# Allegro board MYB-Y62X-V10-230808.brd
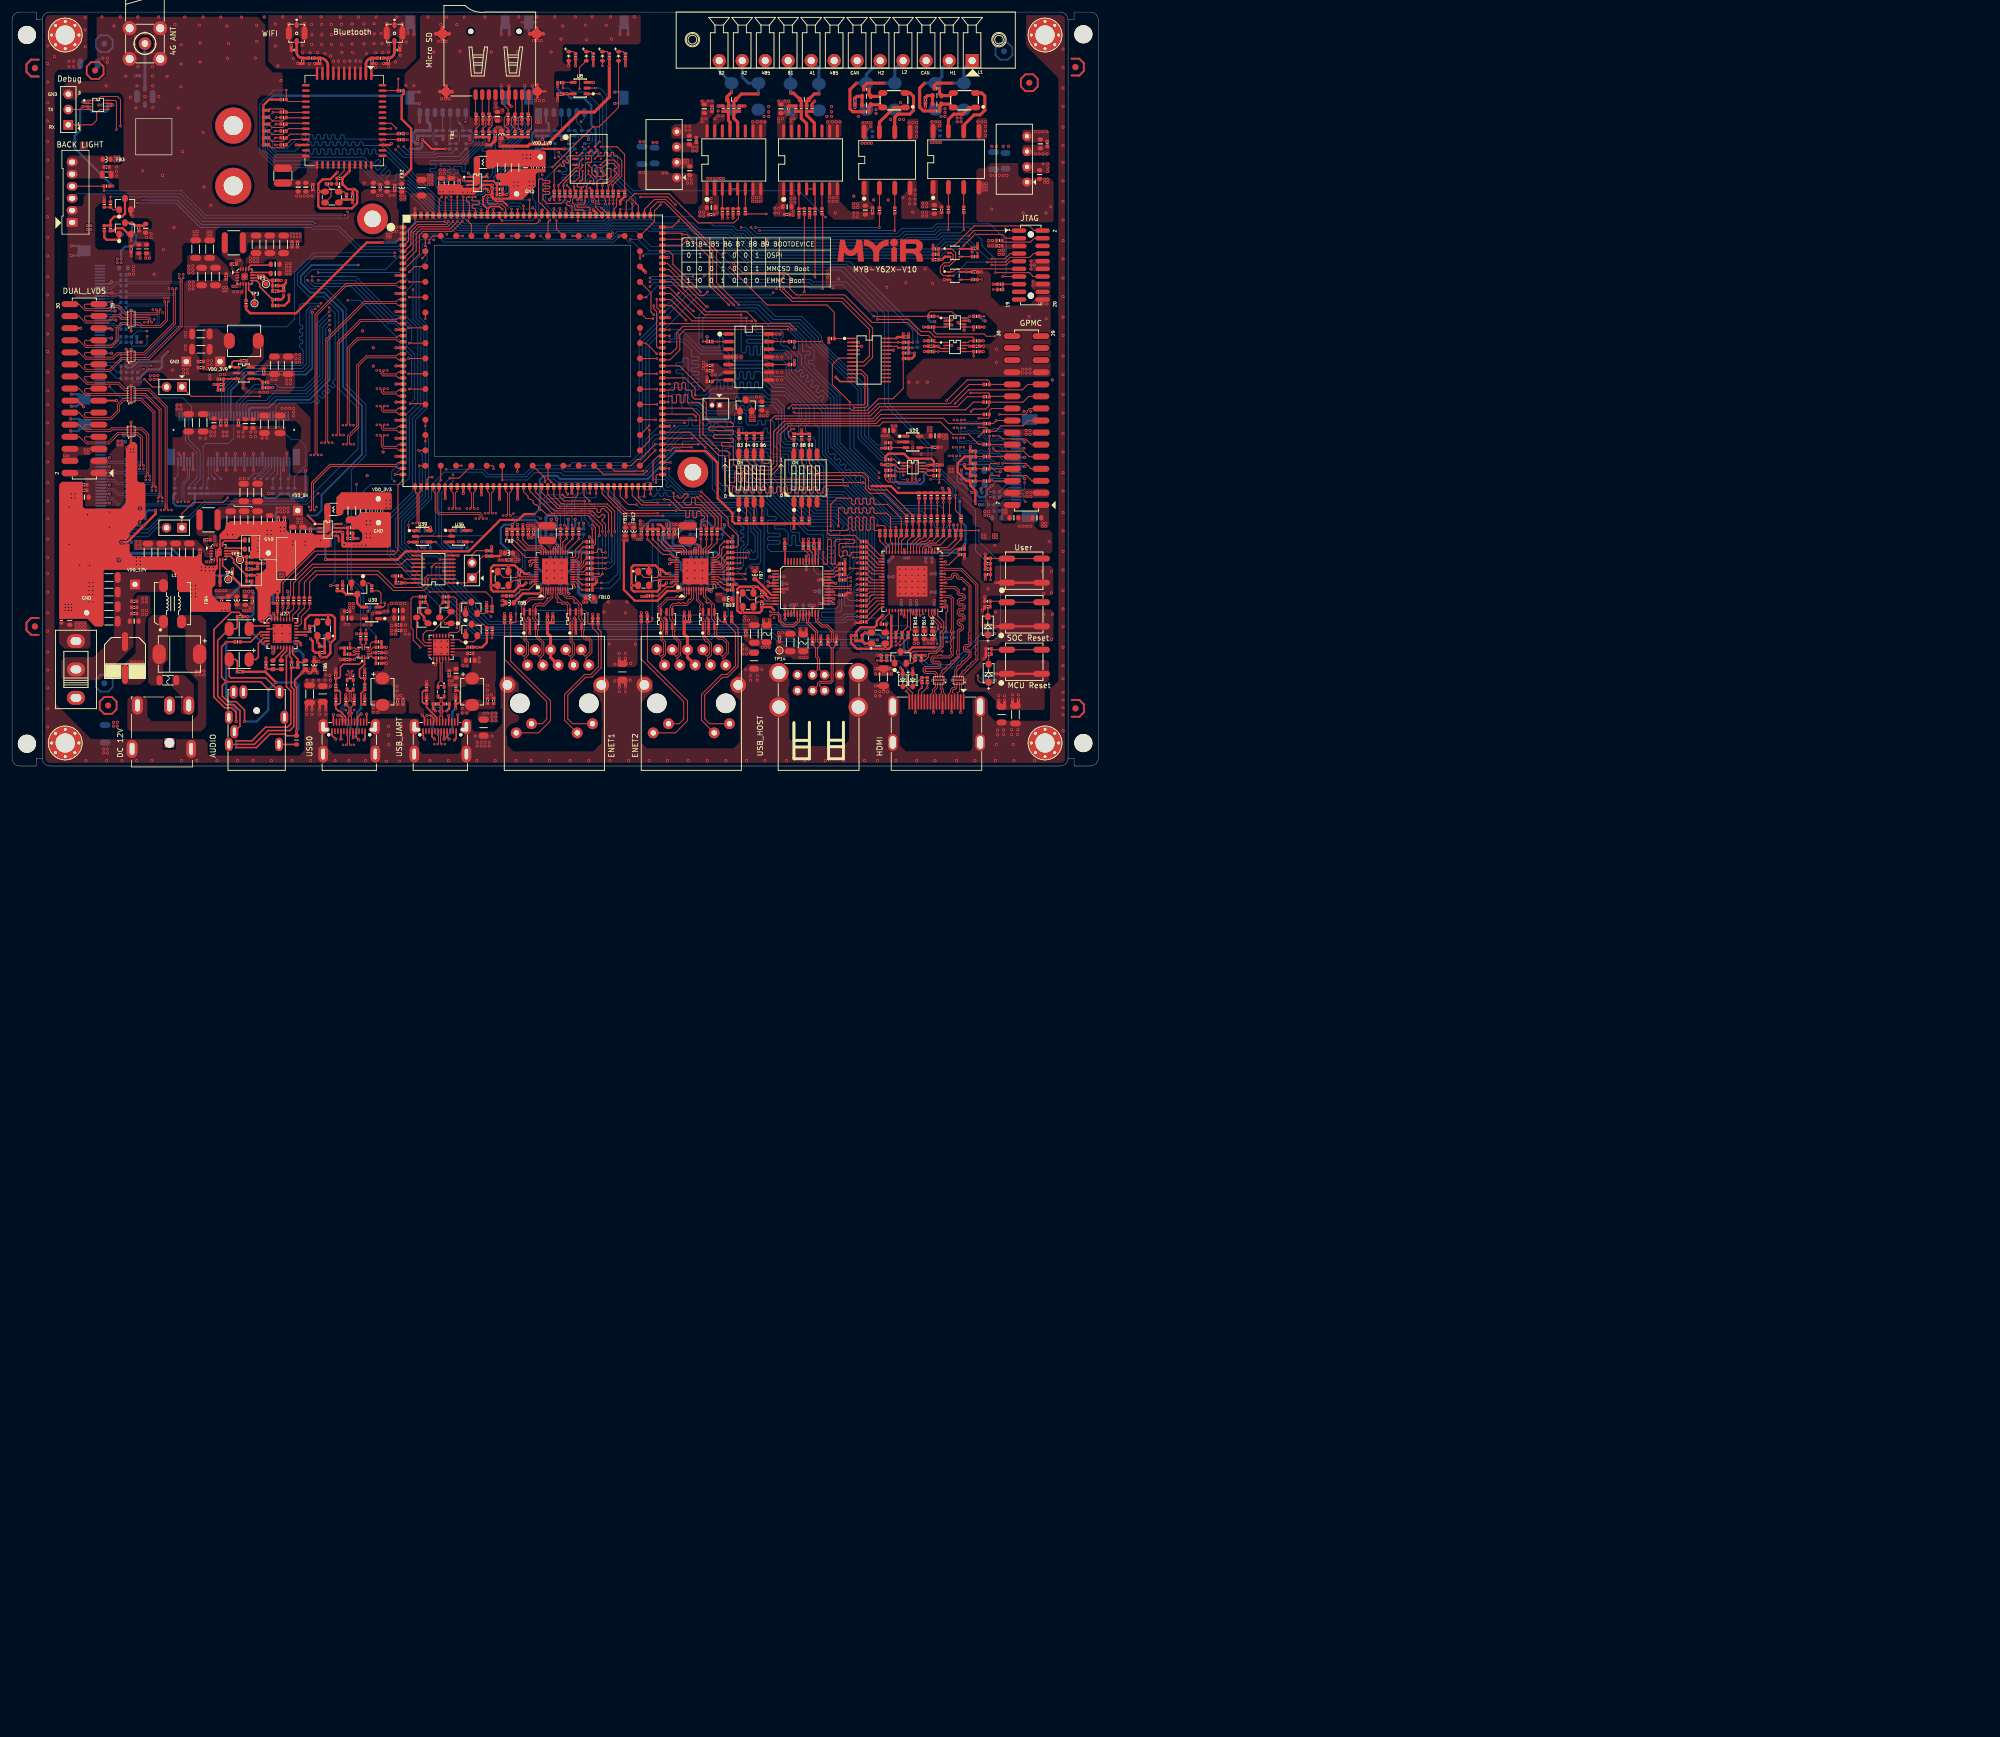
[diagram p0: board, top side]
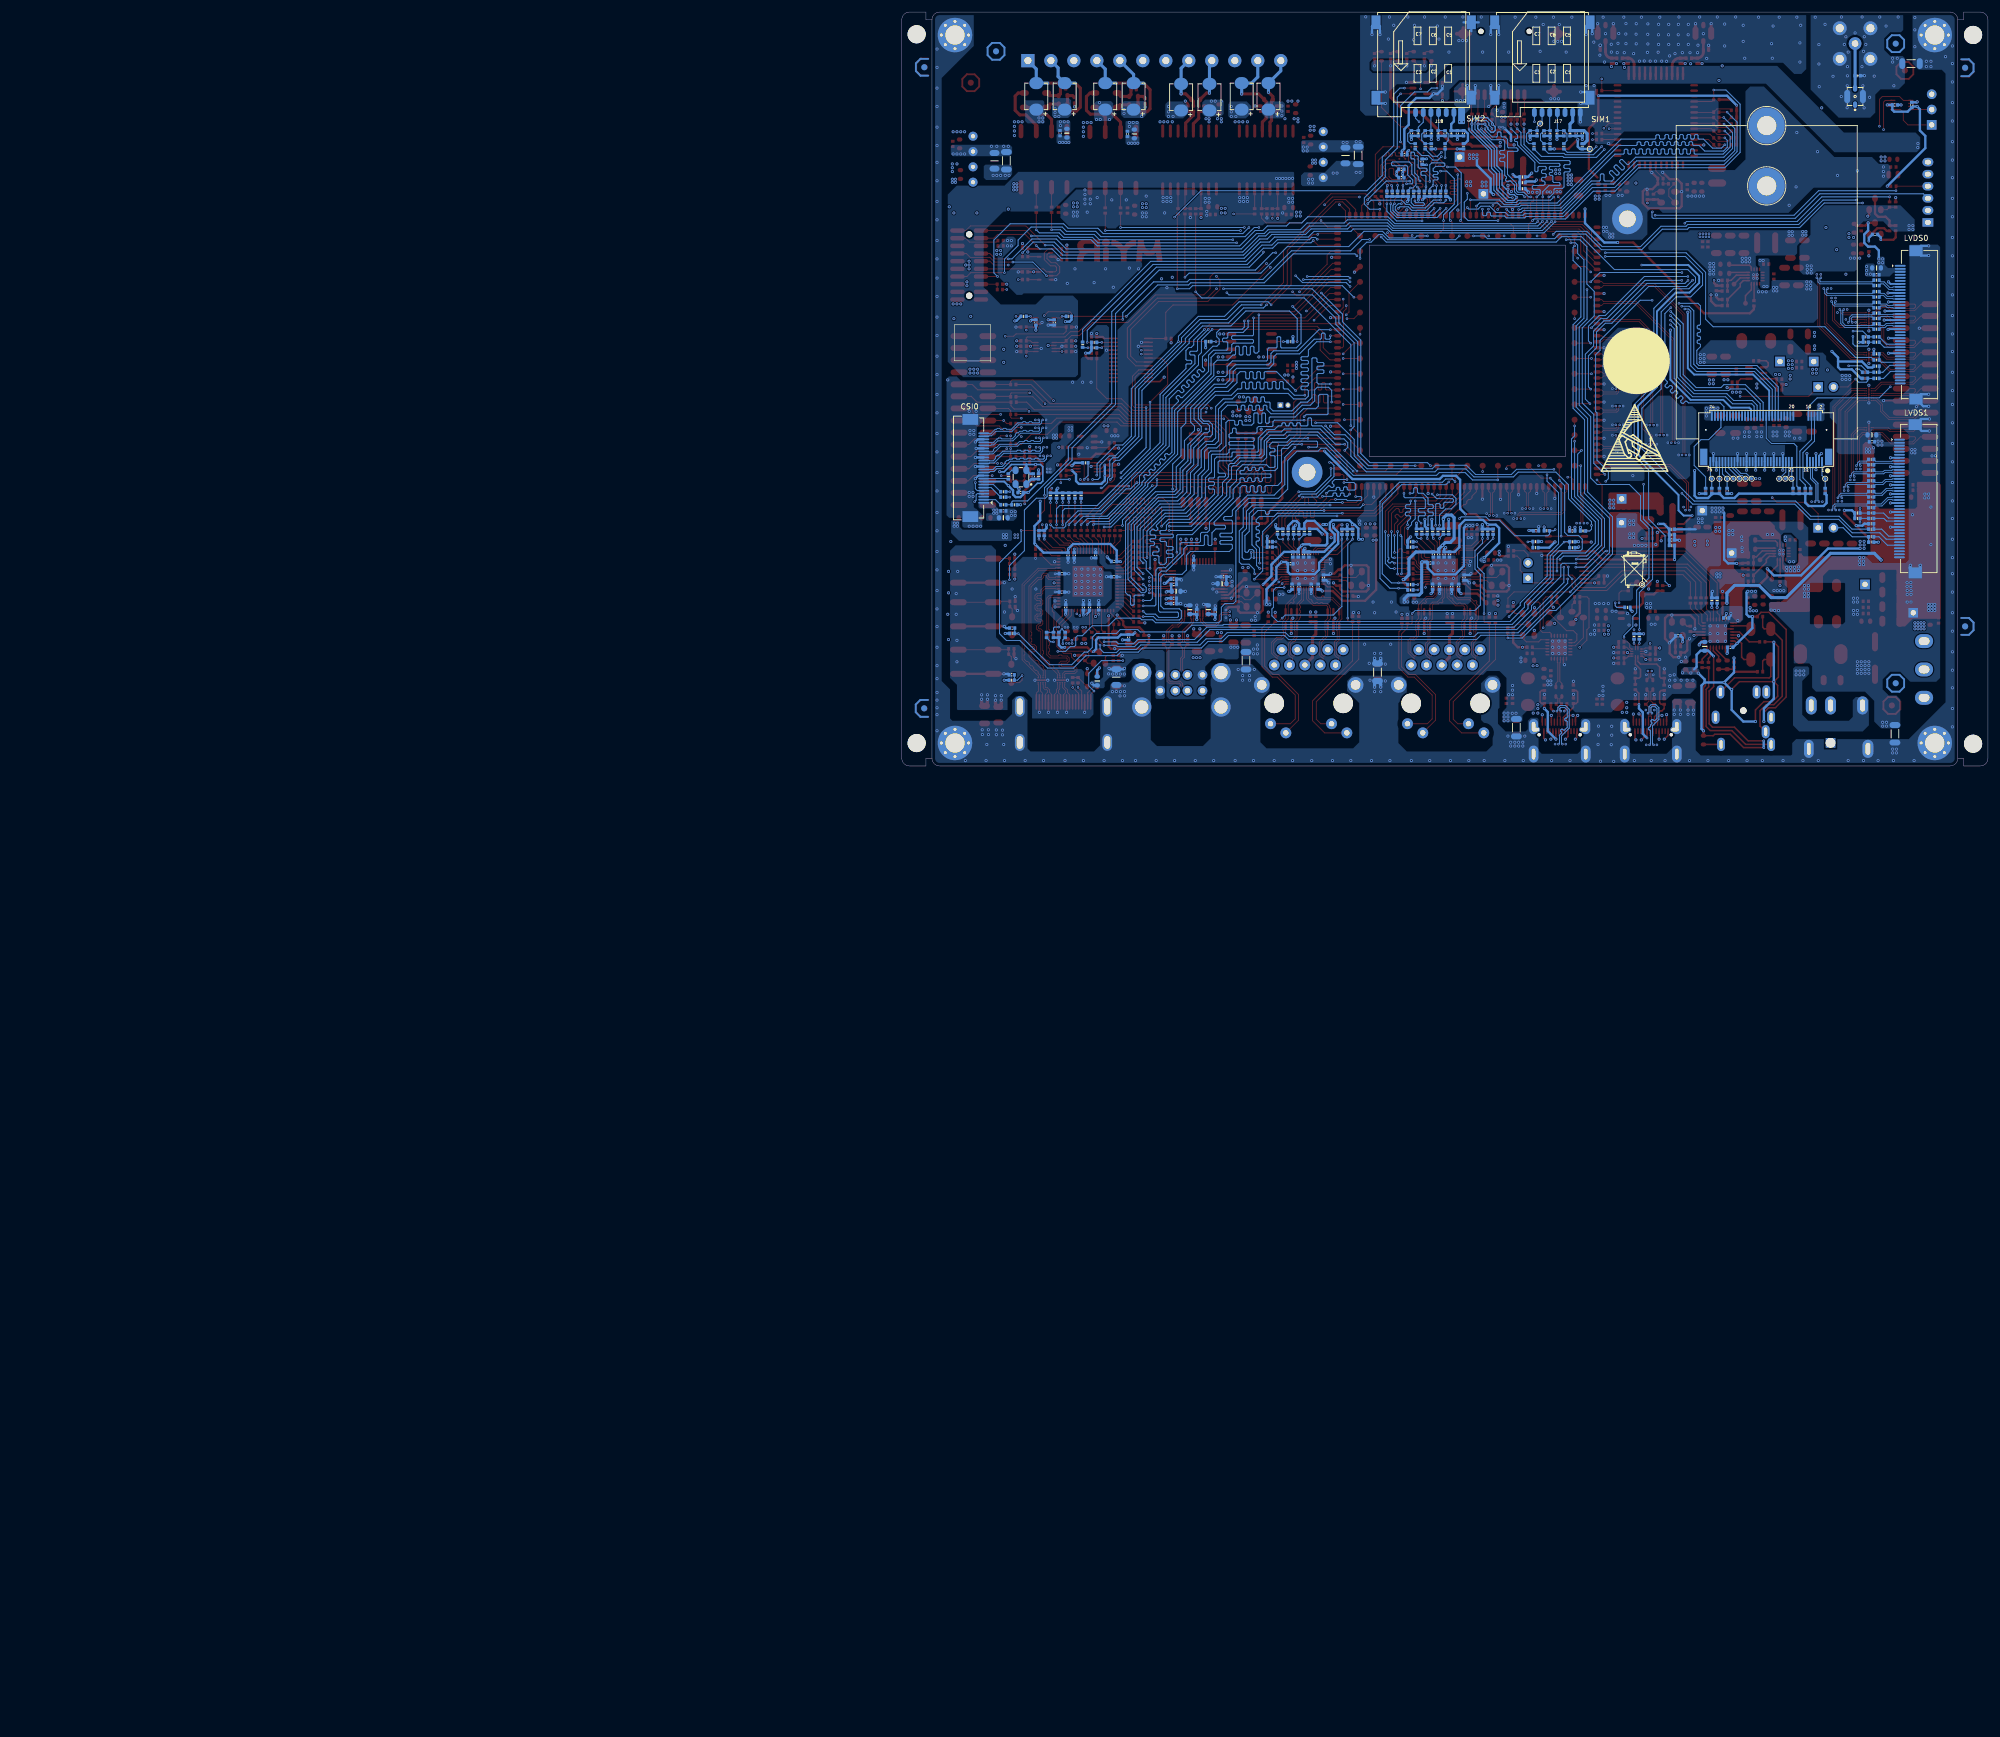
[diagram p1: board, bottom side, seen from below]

Outline 180 x 125 mm; copper layers: TOP, GND02, ART03, POW04, GND05, BOTTOM. Coordinates in mm from the lower left corner of the outline.
Outline path: 5,123.73 4,123.73 4,125 1.27,125 arc(0.37,124.63) 0,123.73 0,1.27 arc(0.37,0.37) 1.27,0 4,0 4,1.27 5,1.27 ; 5,123.73 arc(5.37,124.63) 6.27,125 173.73,125 arc(174.63,124.63) 175,123.73 ; 5,123.73 5,1.27 ; 5,1.27 arc(5.37,0.37) 6.27,0 173.73,0 arc(174.63,0.37) 175,1.27 ; 175,123.73 175,1.27 ; 175,123.73 176,123.73 176,125 178.73,125 arc(179.63,124.63) 180,123.73 180,1.27 arc(179.63,0.37) 178.73,0 176,0 176,1.27 175,1.27 ; 70.02,86.36 70.02,51.31 102.54,51.31 102.54,86.36 70.02,86.36

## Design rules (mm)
net group AUD_MCASP0_ACLKX: nets AUD_MCASP0_ACLKX I2S_SCLK
net group AUD_MCASP0_AFSX: nets AUD_MCASP0_AFSX I2S_LRCLK
net group AUD_MIC: nets AUD_MIC MIC_BIAS
net group AUDIO_MCLK: nets AUDIO_MCLK N20656670
net group CAM_P1_MCLK: nets CAM_P1_MCLK N20386876
net group CAM_RST: nets CAM_RST N20386882
net group CANH1: nets CANH1 N22767928
net group CANH2: nets CANH2 N22768270
net group CANL1: nets CANL1 N22767957
net group CSI_PWDN: nets CSI_PWDN N20386885
net group DEBUG_USB: nets DEBUG_USB_DM DEBUG_USB_DP
net group DIFFPAIR0: nets N22324946 N22324958
net group DPETH1_MD1_: nets ETH1_MD1_N ETH1_MD1_P
net group DPETH1_MD2_: nets ETH1_MD2_N ETH1_MD2_P
net group DPETH1_MD3_: nets ETH1_MD3_N ETH1_MD3_P
net group DPETH1_MD4_: nets ETH1_MD4_N ETH1_MD4_P
net group DPETH2_MD1_: nets ETH2_MD1_N ETH2_MD1_P
net group DPETH2_MD2_: nets ETH2_MD2_N ETH2_MD2_P
net group DPETH2_MD3_: nets ETH2_MD3_N ETH2_MD3_P
net group DPETH2_MD4_: nets ETH2_MD4_N ETH2_MD4_P
net group DPLVDS0_CLK: nets LVDS0_CLKN LVDS0_CLKP
net group DPLVDS0_D0: nets LVDS0_D0N LVDS0_D0P
net group DPLVDS0_D1: nets LVDS0_D1N LVDS0_D1P
net group DPLVDS0_D2: nets LVDS0_D2N LVDS0_D2P
net group DPLVDS0_D3: nets LVDS0_D3N LVDS0_D3P
net group DPLVDS1_CLK: nets LVDS1_CLKN LVDS1_CLKP
net group DPLVDS1_D0: nets LVDS1_D0N LVDS1_D0P
net group DPLVDS1_D1: nets LVDS1_D1N LVDS1_D1P
net group DPLVDS1_D2: nets LVDS1_D2N LVDS1_D2P
net group DPLVDS1_D3: nets LVDS1_D3N LVDS1_D3P
net group HDMI_CONN_CLK: nets HDMI_CONN_CLKN HDMI_CONN_CLKP
net group HDMI_CONN_TX0: nets HDMI_CONN_TX0N HDMI_CONN_TX0P
net group HDMI_CONN_TX1: nets HDMI_CONN_TX1N HDMI_CONN_TX1P
net group HDMI_CONN_TX2: nets HDMI_CONN_TX2N HDMI_CONN_TX2P
net group HDMI_I2C_SCL: nets HDMI_I2C_SCL N22724271
net group HDMI_I2C_SDA: nets HDMI_I2C_SDA N22724282
net group HDMI_MCASP0_ACLKX: nets HDMI_MCASP0_ACLKX N22857632
net group HDMI_MCASP0_AFSX: nets HDMI_MCASP0_AFSX N22857662
net group HDMI_MCASP0_AXR: nets HDMI_MCASP0_AXR N22710530
net group HDMI_MCLK: nets HDMI_MCLK MCLK_12M
net group I2S_DIN: nets AUD_MCASP0_AXR0 I2S_DIN
net group I2S_DOUT: nets AUD_MCASP0_AXR1 I2S_DOUT
net group JTAG_CTI_RTCK: nets JTAG_CTI_RTCK N22483568
net group JTAG_CTI_TCK: nets JTAG_CTI_TCK N22483498
net group JTAG_EMU_RSTN: nets JTAG_EMU_RSTN JTAG_EMU_RSTN_R
net group LCD_TP_INTN: nets LCD_TP_INTN LCD_TP_INTN_R
net group LCD_TP_RESET: nets LCD_TP_RESET LCD_TP_RESET_R
net group LVDS0_TP_PEN: nets LVDS0_TP_PEN N22348696
net group LVDS1_TP_PEN: nets LVDS1_TP_PEN N22355619
net group N22683837: nets N22683837 N22683839
net group N22683997: nets N22683997 N22684003
net group OSPI_INTN: nets OSPI_INTN SOC_OSPI0_ECC_FAIL
net group SOC-USB0: nets SOC_USB0_DM SOC_USB0_DP
net group SOC-USB1: nets SOC_USB1_DM SOC_USB1_DP
net group SOC_GPMC0_WAIT1: nets N21683802 SOC_GPMC0_WAIT1
net group SOC_GPMC0_WPN: nets N21683857 SOC_GPMC0_WPN
net group SOC_JTAG_TCK: nets N22483474 SOC_JTAG_TCK
net group SOC_MCU_MCAN0_RX: nets N22767970 SOC_MCU_MCAN0_RX
net group SOC_MCU_MCAN0_TX: nets N22767924 SOC_MCU_MCAN0_TX
net group SOC_MCU_SPI0_D0: nets N20386918 SOC_MCU_SPI0_D0
net group SOC_OSPI0_DQS: nets SOC_OSPI0_DQS SOC_OSPI0_LBCLK
net group SOC_SPI0_CS0: nets N22355541 SOC_SPI0_CS0
net group SOC_SPI0_CS1: nets N22348627 SOC_SPI0_CS1
net group SOC_SPI0_D0: nets N22348634 SOC_SPI0_D0
net group SOC_SPI0_D1: nets N22355547 SOC_SPI0_D1
net group SOC_UART0_TXD: nets N22941387 SOC_UART0_TXD
net group SOC_UART1_DTRN: nets N22768266 SOC_UART1_DTRN
net group SOC_UART1_RIN: nets N22768318 SOC_UART1_RIN
net group SOC_UART1_RXD: nets N22683943 SOC_UART1_RXD
net group SOC_UART1_TXD: nets N22683961 SOC_UART1_TXD
net group SOC_UART4_RXD: nets N21684314 SOC_UART4_RXD
net group SOC_UART4_TXD: nets N21684387 SOC_UART4_TXD
net group SOC_USB0_DRVVBUS: nets N22325338 SOC_USB0_DRVVBUS
net group SOC_USB1_DRVVBUS: nets N21683929 SOC_USB1_DRVVBUS
net group USB0CC1: nets N22325125 USB0CC1
net group USB0CC2: nets N22325136 USB0CC2
net group USB-5G: nets USB_5G_DM USB_5G_DP
net group USB-UART: nets USB_UART_DM USB_UART_DP
net group USB_HUB_RST: nets N21477956 USB_HUB_RST
net group USBA0: nets USBA0_DM USBA0_DP
net group USBA1: nets USBA1_DM USBA1_DP
net group VDD_USIM1: nets N21544762 VDD_USIM1
net group VDD_USIM2: nets N24926165 VDD_USIM2
net group 50 OHM: nets N25388780
net group AUDIO_GND: nets HP_VGND
net group AUDIO_I2C_SCL: nets AUDIO_I2C_SCL I2C_SCL_CSI LCD_I2C_SCL N22863110 SOC_UART1_DCDN
net group CANL2: nets CANL2 N22768305 N22768352
net group HDMI_TX: nets HDMI_CLK+ HDMI_CLK- HDMI_TX0+ HDMI_TX0- HDMI_TX1+ HDMI_TX1- HDMI_TX2+ HDMI_TX2-
net group I2C_SDA_CSI: nets AUDIO_I2C_SDA I2C_SDA_CSI LCD_I2C_SDA SOC_UART1_DSRN
net group ISO_485: nets N21683845 N21683901 N21714485 N21714524 RS485_A1 RS485_A2 RS485_B1 RS485_B2
net group LCD_B3: nets LCD_B3
net group LCD_B4: nets LCD_B4
net group LCD_B5: nets LCD_B5
net group LCD_B6: nets LCD_B6
net group LCD_B7: nets LCD_B7
net group LCD_G1: nets LCD_G1
net group LCD_G2: nets LCD_G2
net group LCD_G4: nets LCD_G4
net group LCD_G5: nets LCD_G5
net group LCD_G6: nets LCD_G6
net group LCD_G7: nets LCD_G7
net group LCD_R0: nets LCD_R0
net group LCD_R1: nets LCD_R1
net group LCD_R2: nets LCD_R2
net group LCD_R3: nets LCD_R3
net group LCD_R4: nets LCD_R4
net group LVDS0_I2C_SCL: nets LVDS0_I2C_SCL N22597309 SOC_I2C1_SCL SOC_I2C1_SCL_R
net group LVDS0_I2C_SDA: nets LVDS0_I2C_SDA SOC_I2C1_SDA SOC_I2C1_SDA_R
net group LVDS1_I2C_SCL: nets LVDS1_I2C_SCL N22863348 RTC_I2C_SCL USB_I2C_SCL
net group LVDS1_I2C_SDA: nets LVDS1_I2C_SDA RTC_I2C_SDA SOC_UART0_RTSN USB_I2C_SDA
net group N20390757: nets N20390701
net group PWR: nets DEBUG_USB_CC1 DEBUG_USB_CC2 DVDD_RGMII1 DVDD_RGMII2 VDD_MMC1_SD VDD_USB_PLL VDDA_PHY1_3V3
net group RST: nets BT_RST ETH1_RST ETH2_RST
net group RST/CLK: nets MODULE_RESET_N OSPI_RSTN SOC_EXT_REFCLK1 SOC_MCU_RESETZ SOC_MCU_SPI0_CLK SOC_SPI0_CLK

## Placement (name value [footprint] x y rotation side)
C1  100nF/4/50V  [C0402]  20.24 27.3 0 top
C2  100nF/4/50V  [C0402]  20.24 25.27 0 top
C3  1uF/6/25V  [C0603]  20.24 24 0 top
C4  100nF/4/50V  [C0402]  20.24 26.29 0 top
C5  22uF/12/25V  [C1206]  16.05 24 180 top
C6  100uF/6x7/25V  [CE6X6]  18.72 17.91 180 top
C7  1nF/12/2kV  [C1206]  15.41 5.33 90 bottom
C8  1nF/12/2kV  [C1206]  12.75 116.46 0 bottom
C9  1uF/6/25V  [C0603]  43.61 83.19 0 top
C10  22uF/12/25V  [C1206]  31.42 81.15 270 top
C11  100nF/4/50V  [C0402]  36.75 83.21 0 top
C12  22uF/12/25V  [C1206]  33.7 81.15 270 top
C13  100nF/4/50V  [C0402]  35.48 81.15 270 top
C14  10nF/4/50V  [C0402]  47.29 86.49 270 top
C15  47uF/12/10V  [C1206]  40.43 86.49 270 top
C16  47uF/12/10V  [C1206]  42.72 86.49 270 top
C17  47uF/12/10V  [C1206]  45 86.49 270 top
C18  100nF/4/50V  [C0402]  46.4 86.49 270 top
C19  2.2nF/4/50V  [C0402]  43.61 78.74 180 top
C20  1uF/6/25V  [C0603]  43.61 81.66 0 top
C21  1uF/6/25V  [C0603]  39.29 37.47 0 top
C22  22uF/12/25V  [C1206]  27.1 35.43 270 top
C23  22uF/12/25V  [C1206]  29.38 35.43 270 top
C24  100nF/4/50V  [C0402]  31.16 35.43 270 top
C25  100nF/4/50V  [C0402]  32.38 37.49 0 top
C26  10nF/4/50V  [C0402]  44.12 40.77 270 top
C27  47uF/12/10V  [C1206]  36.24 40.77 270 top
C28  47uF/12/10V  [C1206]  38.45 40.79 270 top
C29  47uF/12/10V  [C1206]  40.69 40.77 270 top
C30  100nF/4/50V  [C0402]  45.13 40.77 270 top
C31  2.2nF/4/50V  [C0402]  39.29 32.64 180 top
C32  1uF/6/25V  [C0603]  39.29 35.94 0 top
C33  22uF/8/10V  [C0805]  48.18 38.86 270 top
C34  22uF/8/10V  [C0805]  46.53 38.86 270 top
C35  100nF/4/50V  [C0402]  49.45 38.86 270 top
C36  1nF/4/50V  [C0402]  80.82 94.74 180 top
C37  1nF/4/50V  [C0402]  56.05 37.72 180 top
C38  10nF/4/50V  [C0402]  59.48 42.29 270 top
C39  47uF/12/10V  [C1206]  56.31 42.29 270 top
C40  22uF/8/10V  [C0805]  58.21 42.29 270 top
C41  100nF/4/50V  [C0402]  61.26 42.29 270 top
C42  100nF/4/50V  [C0402]  60.37 42.29 270 top
C43  22uF/8/10V  [C0805]  72.82 96.67 270 top
C44  100nF/4/50V  [C0402]  74.09 96.67 270 top
C45  100nF/4/50V  [C0402]  87.12 99.19 270 top
C46  10uF/4/6.3V  [C0402]  86.23 99.19 270 top
C47  22uF/6/6.3V  [C0603]  85.09 99.19 270 top
C54  100nF/4/50V  [C0402]  80.06 104.73 270 top
C55  2.2uF/6/16V  [C0603]  80.44 107.7 270 top
C56  100nF/4/50V  [C0402]  97.2 97.54 0 bottom
C57  100nF/4/50V  [C0402]  90.85 111.38 180 top
C58  100nF/4/50V  [C0402]  96.69 101.35 180 bottom
C59  4.7uF/4/6.3V  [C0402]  93.77 100.2 90 bottom
C60  100nF/4/50V  [C0402]  97.2 98.93 0 bottom
C61  100nF/4/50V  [C0402]  63.42 95.84 270 top
C62  10uF/6/16V  [C0603]  62.15 95.97 270 top
C65  100nF/4/50V  [C0402]  163.62 86.23 180 top
C70  100nF/4/50V  [C0402]  159.56 85.85 0 top
C71  100nF/4/50V  [C0402]  159.56 81.92 0 top
C72  10pF/4/50V  [C0402]  153.08 83.95 0 top
C73  10uF/6/16V  [C0603]  18.46 82.58 0 bottom
C74  10uF/6/16V  [C0603]  19.22 54.89 0 bottom
C75  100nF/4/50V  [C0402]  18.46 81.43 0 bottom
C76  100nF/4/50V  [C0402]  19.22 53.75 0 bottom
C77  100nF/4/50V  [C0402]  19.73 85.72 270 top
C78  100nF/4/50V  [C0402]  18.72 88.14 180 bottom
C79  10uF/6/16V  [C0603]  22.14 89.15 270 top
C80  100nF/4/50V  [C0402]  21 89.15 270 top
C81  10uF/8/25V  [C0805]  15.67 98.04 0 top
C82  100nF/4/50V  [C0402]  15.67 99.31 0 top
C83  100nF/4/50V  [C0402]  163.18 42.29 180 bottom
C84  10uF/6/16V  [C0603]  163.18 41.15 180 bottom
C85  100nF/4/50V  [C0402]  160.32 45.34 180 bottom
C86  100nF/4/50V  [C0402]  158.22 48.01 90 bottom
C87  100nF/4/50V  [C0402]  152.32 69.6 180 top
C88  100nF/4/50V  [C0402]  159.81 69.6 0 top
C89  10uF/6/16V  [C0603]  145.33 55.63 180 top
C90  10uF/6/16V  [C0603]  147.62 14.1 270 bottom
C91  10uF/6/16V  [C0603]  169.85 41.15 180 top
C92  10uF/6/16V  [C0603]  166.04 41.15 0 top
C93  100nF/4/50V  [C0402]  78.79 10.79 90 top
C94  10pF/4/50V  [C0402]  79.8 10.79 90 top
C95  100nF/4/50V  [C0402]  75.93 18.67 0 top
C96  1uF/6/25V  [C0603]  73.58 15.37 270 top
C97  10uF/6/16V  [C0603]  75.93 17.53 0 top
C98  100nF/4/50V  [C0402]  72.44 15.37 270 top
C99  DNP/C1206  [C1206]  78.15 6.35 270 bottom
C100  10uF/6/16V  [C0603]  152.84 92.29 270 top
C101  100nF/4/50V  [C0402]  154.03 92.22 270 top
C102  100nF/4/50V  [C0402]  153.78 104.92 270 bottom
C103  10uF/6/16V  [C0603]  152.63 104.92 270 bottom
C104  47nF/4/50V  [C0402]  151.36 110.38 270 top
C105  10uF/6/16V  [C0603]  170.29 98.06 270 top
C106  10uF/6/16V  [C0603]  170.41 103.14 270 top
C107  DNP/C1206  [C1206]  162.67 100.35 90 bottom
C108  10uF/6/16V  [C0603]  141.41 92.16 270 top
C109  100nF/4/50V  [C0402]  142.6 92.09 270 top
C110  100nF/4/50V  [C0402]  142.6 104.79 270 bottom
C111  10uF/6/16V  [C0603]  141.46 104.79 270 bottom
C112  47nF/4/50V  [C0402]  139.68 110.26 270 top
C113  10uF/6/16V  [C0603]  112.31 98.68 270 top
C114  10uF/6/16V  [C0603]  112.25 103.78 270 top
C115  10uF/6/16V  [C0603]  128.44 92.71 0 top
C116  100nF/4/50V  [C0402]  128.44 91.44 0 top
C117  100nF/4/50V  [C0402]  128.7 108.97 90 top
C118  10uF/6/16V  [C0603]  127.43 108.97 90 top
C119  DNP/C1206  [C1206]  104.37 101.24 90 bottom
C121  10uF/6/16V  [C0603]  115.87 92.58 0 top
C122  100nF/4/50V  [C0402]  115.87 91.44 0 top
C123  100nF/4/50V  [C0402]  116 108.97 90 top
C124  10uF/6/16V  [C0603]  114.73 108.97 90 top
C125  100nF/4/50V  [C0402]  51.35 21.59 0 bottom
C126  100nF/4/50V  [C0402]  51.35 18.8 180 top
C127  100nF/4/50V  [C0402]  46.33 16.74 90 top
C128  1nF/4/50V  [C0402]  37.77 24.77 0 top
C129  1nF/4/50V  [C0402]  37.77 15.62 0 top
C130  1uF/6/25V  [C0603]  48.64 16.74 270 top
C131  100nF/4/50V  [C0402]  42.72 19.68 180 bottom
C132  DNP  [C0603]  46.94 19.84 270 bottom
C133  1uF/6/25V  [C0603]  35.86 27.43 270 top
C134  100nF/4/50V  [C0402]  34.72 27.43 270 top
C135  1uF/6/25V  [C0603]  38.65 27.43 90 top
C136  100nF/4/50V  [C0402]  39.8 27.43 90 top
C137  100nF/4/50V  [C0402]  43.99 27.43 90 top
C138  100nF/4/50V  [C0402]  132.89 36.45 90 top
C139  10uF/6/16V  [C0603]  129.21 25.91 90 bottom
C140  1uF/6/25V  [C0603]  132.25 25.91 90 bottom
C141  100nF/4/50V  [C0402]  131.62 33.66 270 bottom
C142  100nF/4/50V  [C0402]  134.92 30.99 180 bottom
C143  100nF/4/50V  [C0402]  131.11 25.53 90 bottom
C144  100nF/4/50V  [C0402]  128.06 25.53 90 bottom
C145  100nF/4/50V  [C0402]  134.92 27.81 180 bottom
C146  22pF/4/50V  [C0402]  124.25 26.8 270 top
C147  22pF/4/50V  [C0402]  124.25 28.57 90 top
C148  10uF/6/16V  [C0603]  126.92 30.23 0 bottom
C149  1uF/6/25V  [C0603]  134.54 28.96 180 bottom
C150  100nF/4/50V  [C0402]  134.92 30.1 180 bottom
C151  100nF/4/50V  [C0402]  134.92 26.92 180 bottom
C152  100nF/4/50V  [C0402]  126.67 31.37 0 bottom
C153  100nF/4/50V  [C0402]  55.55 17.65 180 top
C154  100nF/4/50V  [C0402]  60.75 18.8 0 top
C155  100nF/4/50V  [C0402]  63.9 10.67 90 top
C156  10pF/4/50V  [C0402]  64.79 10.67 90 top
C157  10uF/6/16V  [C0603]  55.55 24.51 180 top
C158  1nF/4/50V  [C0402]  53.64 14.99 90 top
C159  100nF/4/50V  [C0402]  55.55 25.65 180 top
C160  1nF/4/50V  [C0402]  58.44 14.99 90 top
C161  4.7uF/6/16V  [C0603]  64.05 25.78 0 top
C162  100nF/4/50V  [C0402]  64.05 22.48 0 top
C163  100nF/4/50V  [C0402]  64.05 23.37 0 top
C164  10uF/6/16V  [C0603]  64.05 24.51 0 top
C165  DNP/C1206  [C1206]  49.32 11.94 270 top
C166  47uF/12/10V  [C1206]  123.01 21.89 90 top
C167  100nF/4/50V  [C0402]  121.61 22.05 90 top
C168  100nF/4/50V  [C0402]  127.17 21.05 90 top
C169  47uF/12/10V  [C1206]  128.95 20.47 90 top
C170  DNP/C1206  [C1206]  144.42 14.73 270 top
C171  100nF/4/50V  [C0402]  38.4 67.18 0 top
C172  22uF/12/25V  [C1206]  43.48 66.42 270 top
C173  22uF/12/25V  [C1206]  45.77 66.42 270 top
C174  100nF/4/50V  [C0402]  41.7 65.41 270 top
C175  33pF/4/50V  [C0402]  68.25 104.9 270 bottom
C176  100nF/4/50V  [C0402]  67.23 104.9 270 bottom
C177  1nF/4/50V  [C0402]  34.59 63.25 0 top
C178  DNP  [C1206]  31.29 71.63 180 top
C179  22uF/12/25V  [C1206]  31.29 69.09 180 top
C180  100nF/4/50V  [C0402]  31.29 67.06 180 top
C181  100nF/4/50V  [C0402]  31.29 66.04 180 top
C182  33pF/4/50V  [C0402]  70.28 104.9 270 bottom
C183  33pF/4/50V  [C0402]  75.87 104.9 270 bottom
C184  33pF/4/50V  [C0402]  73.58 104.9 270 bottom
C185  100uF/12/6.3V  [C1206]  29.26 56.9 270 top
C186  100uF/12/6.3V  [C1206]  41.83 56.64 270 top
C187  10uF/6/16V  [C0603]  33.45 56.9 270 top
C188  100nF/4/50V  [C0402]  37.51 56.9 270 top
C189  100uF/12/6.3V  [C1206]  31.67 56.9 270 top
C190  100uF/12/6.3V  [C1206]  44.37 56.64 270 top
C191  10uF/6/16V  [C0603]  38.65 56.77 270 top
C192  1uF/6/25V  [C0603]  39.92 56.77 270 top
C193  33pF/4/50V  [C0402]  34.59 56.9 270 top
C194  10nF/4/50V  [C0402]  35.48 56.9 270 top
C195  33pF/4/50V  [C0402]  87.93 104.9 270 bottom
C196  100nF/4/50V  [C0402]  86.91 104.9 270 bottom
C197  33pF/4/50V  [C0402]  89.96 104.9 270 bottom
C198  33pF/4/50V  [C0402]  95.55 104.9 270 bottom
C199  33pF/4/50V  [C0402]  93.26 104.9 270 bottom
C200  10nF/4/50V  [C0402]  43.23 45.59 270 bottom
C201  33pF/4/50V  [C0402]  84.03 32.1 90 top
C202  10nF/4/50V  [C0402]  89.62 24.23 90 top
C203  100nF/4/50V  [C0402]  88.73 24.23 90 top
C204  DNP/C1206  [C1206]  122.96 17.45 90 bottom
C205  33pF/4/50V  [C0402]  84.03 30.32 270 top
C206  4.7uF/4/6.3V  [C0402]  85.56 38.83 270 top
C207  100nF/4/50V  [C0402]  86.44 38.83 270 top
C208  100nF/4/50V  [C0402]  74.89 38.99 180 bottom
C209  4.7uF/4/6.3V  [C0402]  91.02 35.05 270 bottom
C210  100nF/4/50V  [C0402]  91.91 35.05 270 bottom
C211  100nF/4/50V  [C0402]  92.41 33.66 180 bottom
C212  100nF/4/50V  [C0402]  87.71 29.72 90 bottom
C213  100nF/4/50V  [C0402]  92.03 29.72 90 bottom
C214  4.7uF/4/6.3V  [C0402]  82.34 34.16 180 top
C215  100nF/4/50V  [C0402]  89.24 35.05 270 bottom
C216  100nF/4/50V  [C0402]  90.13 35.05 270 bottom
C217  100nF/4/50V  [C0402]  90.89 29.72 90 bottom
C218  100nF/4/50V  [C0402]  88.86 29.72 90 bottom
C219  100nF/4/50V  [C0402]  86.83 31.24 90 bottom
C220  33pF/4/50V  [C0402]  107.32 32.1 90 top
C221  10nF/4/50V  [C0402]  112.28 24.36 90 top
C222  100nF/4/50V  [C0402]  111.39 24.36 90 top
C223  DNP/C1206  [C1206]  101.16 15.54 90 bottom
C224  33pF/4/50V  [C0402]  107.32 30.32 270 top
C225  4.7uF/4/6.3V  [C0402]  108.85 38.83 270 top
C226  100nF/4/50V  [C0402]  115.58 33.53 180 bottom
C227  100nF/4/50V  [C0402]  68.88 38.96 180 bottom
C228  4.7uF/4/6.3V  [C0402]  114.31 35.05 270 bottom
C229  100nF/4/50V  [C0402]  115.2 35.05 270 bottom
C230  100nF/4/50V  [C0402]  109.74 38.83 270 top
C231  100nF/4/50V  [C0402]  115.33 29.72 90 bottom
C232  100nF/4/50V  [C0402]  111.01 29.72 90 bottom
C233  4.7uF/4/6.3V  [C0402]  112.53 35.05 270 bottom
C234  100nF/4/50V  [C0402]  104.28 38.86 90 top
C235  100nF/4/50V  [C0402]  113.42 35.05 270 bottom
C236  100nF/4/50V  [C0402]  114.18 29.72 90 bottom
C237  100nF/4/50V  [C0402]  112.15 29.72 90 bottom
C238  100nF/4/50V  [C0402]  110.12 31.24 90 bottom
C239  100nF/4/50V  [C0402]  161.84 18.54 180 top
C240  100nF/4/50V  [C0402]  161.78 15.11 0 bottom
C241  100nF/4/50V  [C0402]  161.65 26.42 180 top
C242  100nF/4/50V  [C0402]  161.72 22.86 0 bottom
C247  100nF/4/50V  [C0402]  161.72 33.53 180 top
C248  100nF/4/50V  [C0402]  161.72 32.64 180 top
C249  10uF/6/16V  [C0603]  124.25 59.69 270 top
C250  100nF/4/50V  [C0402]  115.62 65.53 180 top
C251  100nF/4/50V  [C0402]  115.62 66.42 180 top
C253  100nF/4/50V  [C0402]  148.13 71.12 0 top
C256  10uF/6/16V  [C0603]  11.98 44.58 180 top
C257  100nF/4/50V  [C0402]  11.98 45.72 180 top
C258  100nF/4/50V  [C0402]  11.98 46.61 180 top
C259  100nF/4/50V  [C0402]  154.73 73.53 90 bottom
C260  100nF/4/50V  [C0402]  157.78 73.53 270 bottom
C261  100nF/4/50V  [C0402]  12.62 109.6 90 bottom
C262  100nF/4/50V  [C0402]  15.41 109.6 180 bottom
C263  DNP  [C0402]  59.65 116.92 270 top
C264  DNP  [C0402]  62.36 116.92 270 top
C265  DNP  [C0402]  50.97 116.92 270 top
C266  DNP  [C0402]  48.18 116.92 270 top
C269  100nF/4/50V  [C0402]  61.01 95.97 270 top
C270  10uF/6/16V  [C0603]  59.86 95.97 270 top
C271  DNP  [C0402]  56.43 94.36 90 top
C272  DNP  [C0402]  54.28 97.41 0 top
C273  10uF/6/16V  [C0603]  47.42 95.97 270 top
C274  10uF/6/16V  [C0603]  48.69 95.97 270 top
C275  100nF/4/50V  [C0402]  49.83 95.97 270 top
C278  1uF/6/25V  [C0603]  152.95 54.74 0 top
C279  DNP/C1206  [C1206]  166.29 8.51 90 top
C280  100nF/4/50V  [C0402]  145.21 49.91 180 top
C281  100nF/4/50V  [C0402]  153.21 49.91 0 top
C282  100nF/4/50V  [C0402]  151.43 34.92 270 bottom
C283  100nF/4/50V  [C0402]  147.37 26.29 90 bottom
C284  100nF/4/50V  [C0402]  144.83 31.37 0 bottom
C285  100nF/4/50V  [C0402]  147.87 34.92 270 bottom
C286  100nF/4/50V  [C0402]  152.83 26.29 90 bottom
C287  100nF/4/50V  [C0402]  149.91 26.29 90 bottom
C288  100nF/4/50V  [C0402]  148.89 26.29 90 bottom
C289  100nF/4/50V  [C0402]  144.83 33.91 0 bottom
C290  100nF/4/50V  [C0402]  152.45 34.92 270 bottom
C291  100nF/4/50V  [C0402]  153.46 28.83 180 bottom
C292  100nF/4/50V  [C0402]  153.46 31.88 180 bottom
C293  100nF/4/50V  [C0402]  142.41 21.34 270 bottom
C294  100nF/4/50V  [C0402]  139.87 21.21 90 top
C318  10nF/4/50V  [C0402]  152.95 52.83 0 top
C319  100nF/4/50V  [C0402]  64.05 30.35 180 top
C320  1uF/4/6.3V  [C0402]  52.37 37.47 180 bottom
C321  1uF/6/25V  [C0603]  44.62 16.76 270 top
C322  1uF/6/25V  [C0603]  43.23 16.76 270 top
C323  47uF/12/10V  [C1206]  81.07 99.19 270 top
C324  10nF/4/50V  [C0402]  88.08 99.19 270 top
C325  22uF/8/10V  [C0805]  71.17 96.67 270 top
C328  47uF/12/10V  [C1206]  40.69 45.34 90 top
C329  47uF/12/10V  [C1206]  38.4 45.34 90 top
C330  22uF/8/10V  [C0805]  42.72 40.77 270 top
C331  47uF/12/10V  [C1206]  83.36 99.19 270 top
C332  22uF/12/25V  [C1206]  16.05 31.24 180 top
C333  22uF/12/25V  [C1206]  16.05 26.42 180 top
C334  22uF/12/25V  [C1206]  30.43 85.7 90 top
C335  22uF/12/25V  [C1206]  32.74 85.7 90 top
C336  22uF/12/25V  [C1206]  24.81 35.41 270 top
C337  22uF/12/25V  [C1206]  22.53 35.41 270 top
C338  22uF/12/25V  [C1206]  16.05 28.83 180 top
CT1  100uF/3528/10V  [CT3528-B]  37.64 17.65 180 top
CT2  100uF/3528/10V  [CT3528-B]  37.64 22.73 180 top
D1  SMCJ15CA  [DO-214AB]  27.73 18.54 180 top
D2  B72590D50H160  [D0402]  76.88 107.65 90 top
D3  B72590D50H160  [D0402]  78.02 107.65 90 top
D4  B72590D50H160  [D0402]  79.04 107.65 90 top
D5  B72590D50H160  [D0402]  82.22 107.65 90 top
D6  B72590D50H160  [D0402]  83.36 107.65 90 top
D7  B72590D50H160  [D0402]  84.5 107.65 90 top
D8  B72590D50H160  [D0402]  85.52 107.65 90 top
D9  SMBJ6.0CA  [DO-214AA]  76.25 12.32 270 top
D10  B72590D50H160  [D0402]  72 10.29 180 top
D11  B72590D50H160  [D0402]  70.22 10.29 0 top
D12  B72590D50H160  [D0402]  68.69 10.79 270 top
D13  B72590D50H160  [D0402]  73.52 10.79 270 top
D14  SMBJ12CA  [DO-214AA]  119.23 111.02 90 bottom
D15  SMBJ12CA  [DO-214AA]  123.68 111.02 90 bottom
D16  SMBJ12CA  [DO-214AA]  129.01 110.89 90 bottom
D17  SMBJ12CA  [DO-214AA]  133.71 110.89 90 bottom
D18  SMBJ12CA  [DO-214AA]  141.59 111.02 90 bottom
D19  SMBJ12CA  [DO-214AA]  146.28 111.02 90 bottom
D20  SMBJ12CA  [DO-214AA]  153.02 111.02 90 bottom
D21  SMBJ12CA  [DO-214AA]  157.71 111.02 90 bottom
D22  SMBJ6.0CA  [DO-214AA]  61.39 12.32 270 top
D23  B72590D50H160  [D0402]  55.31 10.67 270 top
D24  B72590D50H160  [D0402]  56.71 10.67 270 top
D25  B72590D50H160  [D0402]  53.66 10.67 270 top
D26  B72590D50H160  [D0402]  58.44 10.67 270 top
D27  B72590D50H160  [D0402]  132.63 20.57 270 top
D28  B72590D50H160  [D0402]  134.03 20.57 270 top
D29  B72590D50H160  [D0402]  136.6 20.57 270 top
D30  B72590D50H160  [D0402]  135.2 20.57 270 top
D31  B72590D50H160  [D0402]  69.26 104.9 90 bottom
D32  B72590D50H160  [D0402]  71.42 104.9 90 bottom
D33  B72590D50H160  [D0402]  74.72 104.9 90 bottom
D34  B72590D50H160  [D0402]  72.56 104.9 90 bottom
D35  B72590D50H160  [D0402]  88.95 104.9 90 bottom
D36  B72590D50H160  [D0402]  91.11 104.9 90 bottom
D37  B72590D50H160  [D0402]  94.41 104.9 90 bottom
D38  B72590D50H160  [D0402]  92.25 104.9 90 bottom
D39  DNP  [D0402]  21.58 114.45 0 bottom
D40  B72590D50H160  [D0402]  82.63 24.23 270 top
D41  B72590D50H160  [D0402]  96.22 24 270 top
D42  B72590D50H160  [D0402]  105.29 24.36 270 top
D43  B72590D50H160  [D0402]  118.12 24.36 270 top
D44  LMBR120FT1G  [SOD123]  161.84 15.37 90 top
D45  B72590D50H160  [D0402]  161.84 19.43 0 top
D46  LMBR120FT1G  [SOD123]  161.72 23.24 90 top
D47  B72590D50H160  [D0402]  161.65 27.3 0 top
D48  LBAT54CLT1G  [SOT-23]  121.59 59.82 0 top
D49  B72590D50H160  [D0402]  161.72 34.42 0 top
D50  Green  [LED0603]  92.25 117.68 270 top
D53  Blue  [LED0603]  100.5 117.68 270 top
D54  Blue  [LED0603]  97.84 117.68 270 top
D55  Blue  [LED0603]  95.17 117.68 270 top
D56  B72590D50H160  [D0402]  63.82 118.7 180 top
D57  B72590D50H160  [D0402]  46.72 118.7 0 top
D58  RB751V40,115  [SOD323]  147.62 14.22 90 top
D59  RB751V40,115  [SOD323]  149.27 14.22 90 top
F1  4A/72V  [F1206]  25.83 14.22 180 top
F2  0.75A  [F1206]  125.04 21.89 90 top
F3  0.75A  [F1206]  131.11 20.42 90 top
FB1  220R/1.5A  [FB0603]  81.07 104.73 90 top
FB2  220R/1.5A  [FB0603]  64.56 95.84 270 top
FB3  220R/1.5A  [FB0603]  15.67 100.58 0 top
FB4  220R/1.5A  [FB0603]  37.26 27.43 270 top
FB6  220R/1.5A  [FB0603]  50.08 16.66 270 top
FB7  220R/1.5A  [FB0603]  123.11 31.62 270 top
FB8  220R/1.5A  [FB0603]  82.47 27.05 0 top
FB9  220R/1.5A  [FB0603]  82.34 35.31 0 top
FB10  220R/1.5A  [FB0603]  95.72 27.94 180 top
FB11  220R/1.5A  [FB0603]  101.61 38.86 270 top
FB12  220R/1.5A  [FB0603]  103.01 38.86 270 top
FB13  220R/1.5A  [FB0603]  118.66 27.69 180 top
FB14  220R/1.5A  [FB0603]  151.18 21.72 270 top
FB15  220R/1.5A  [FB0603]  152.57 21.69 270 top
FB16  220R/1.5A  [FB0603]  149.74 21.69 270 top
J1  738-03220009  [738-032XX009]  26.08 3.84 90 top
J2  MR01A-01211  [SD-MR01A-01211]  79.17 118.7 180 top
J4  1325-1210G0M087CR01  [CONN2X10-1_27]  168.83 83.06 270 top
J5  FPC05040-17205  [FPC40-0_5-H]  12.24 73.18 90 bottom
J6  FPC05040-17205  [FPC40-0_5-H]  12.37 44.35 90 bottom
J7  B6B-PH-K-S  [CONN-B6B-PH-K]  9.95 95.12 270 top
J8  13201215CNG4M80T01  [CONN2X15-2_00-SMD]  11.98 62.58 90 top
J9  FPC05024-17205  [FPC24-0_5-H]  166.22 49.4 270 bottom
J11  13201215CNG4M80T01  [CONN2X15-2_00-SMD]  168.13 57.28 90 top
J12  -  [UT12111-B1609-7F]  70.98 3.17 0 top
J13  ULO-TB13-15RM/3.81-12P-4000A  [TP381-12PINS-90-W]  138.16 120.35 0 top
J14  JA41131-34BCB-7H  [AUDIO-JA41131-34BCB-7H]  40.53 9.17 0 top
J15  -  [UT12111-B1609-7F]  55.88 3.17 0 top
J16  -  [UB11121-8FDE-4F]  133.66 8.28 180 top
J17  SI62C-01200  [SIM-SI62C-01200]  73.83 117.05 0 bottom
J18  SI62C-01200  [SIM-SI62C-01200]  93.52 117.05 0 bottom
J19  APCI0105-P001A  [CONN-2199230-3]  36.75 54.36 0 bottom
J20  FC-SMA271  [ANT-5PINS]  22.02 119.78 90 top
J21  1566230-1  [ANT-1566230-1]  22.02 111 90 bottom
J22  -  [S11-ZZ-0319]  89.87 10.39 0 top
J23  -  [S11-ZZ-0319]  112.57 10.39 0 top
J25  530470210  [CONN1X2-1_25-DIP]  116.63 59.82 0 top
J26  1125-1103G0S116C001  [CONN1X3-2_54-DIP]  9.32 108.84 180 top
J27  ANB02001-125  [ANT-1566230-1]  63.38 121.49 270 top
J28  ANB02001-125  [ANT-1566230-1]  47.16 121.49 270 top
J29  QJ51191-LFB4-7F  [QJ51191-LFB4]  153.2 6.89 0 top
JP1  12251102CNG4S115001  [CONN1X2-2_54-DIP]  76.22 32.41 180 top
JP2  12251102CNG4S115001  [CONN1X2-2_54-DIP]  26.87 39.5 270 top
JP3  12251102CNG4S115001  [CONN1X2-2_54-DIP]  26.87 62.84 270 top
L1  100MHz/80V/5A  [INDCM-ACM7060]  26.59 26.92 90 top
L2  1.0uH/26mR/11.1A  [L4_0X4_0]  36.75 86.74 0 top
L3  1.0uH/26mR/11.1A  [L4_0X4_0]  32.56 40.82 0 top
L4  1.0uH/32mR/5.2A  [L2X2_5]  53.26 42.55 0 top
L5  1.0uH/32mR/5.2A  [L2X2_5]  78.02 100.08 0 top
L6  90ohm/280mA  [INDCM-SDCW2012]  71.11 12.32 270 top
L7  2.8kohm/200mA  [INDCM-ACT45B]  157.84 110.38 180 top
L8  2.8kohm/200mA  [INDCM-ACT45B]  146.16 110.38 180 top
L9  90ohm/280mA  [INDCM-SDCW2012]  56.03 13.46 270 top
L10  2.2uH/35mR/5.5A  [L5_2X5_5]  38.4 70.48 270 top
L11  2.2uH  [L3X3]  88.69 38.61 180 top
L12  2.2uH  [L3X3]  111.93 38.61 180 top
L13  2.2uH  [L3X3]  44.88 97.87 180 top
MTG1  MHOLE  [HOLE3_2P-8]  8.81 121.19 0 top
MTG2  MHOLE  [HOLE3_2P-8]  171.19 121.19 0 top
MTG3  MHOLE  [HOLE3_2P-8]  8.81 3.81 0 top
MTG4  MHOLE  [HOLE3_2P-8]  171.19 3.81 0 top
MTG6  -  [MH236-125T]  36.66 96.18 180 bottom
MTG9  -  [MH236-125T]  36.66 106.18 180 bottom
MTG10  MH236-125T  [GNDPOINT256]  59.74 90.71 0 top
MTG11  MH236-125T  [GNDPOINT256]  112.83 48.71 0 top
NOREF  -  [unnamed]  177.54 3.79 180 top
NOREF#2  -  [#2]  435.12 -1.35 0 top
NOREF#3  -  [unnamed#3]  176.23 9.55 180 top
NOREF#4  -  [unnamed]  177.54 121.32 0 top
NOREF#5  -  [unnamed]  2.46 3.68 180 top
NOREF#6  -  [#2]  466.54 84.05 0 top
NOREF#7  -  [#2]  5 1.27 0 top
NOREF#8  -  [#2]  435.48 -46.51 0 top
NOREF#9  -  [unnamed#3]  3.78 23.14 180 top
NOREF#10  -  [unnamed]  2.46 121.2 0 top
NOREF#11  -  [#2]  441.63 144.78 0 top
NOREF#12  -  [unnamed#3]  13.76 115.32 180 top
NOREF#13  -  [unnamed#3]  15.92 10.03 180 top
NOREF#14  -  [unnamed#3]  168.58 113.28 180 top
NOREF#15  -  [#2]  6.27 0 90 top
NOREF#16  -  [unnamed#3]  176.22 115.88 0 top
NOREF#17  -  [unnamed#3]  3.78 115.69 0 top
NOREF#18  -  [#2]  467.08 8.51 0 top
NOREF#19  -  [#2]  164.51 73.03 180 bottom
NOREF#20  -  [unnamed#3]  164.38 118.49 0 bottom
NOREF#21  -  [unnamed#3]  3.78 115.77 0 bottom
NOREF#22  -  [unnamed#3]  176.3 9.55 0 bottom
NOREF#23  -  [unnamed#3]  3.78 23.14 0 bottom
NOREF#24  -  [#2]  58.97 53.98 180 bottom
NOREF#25  -  [unnamed#3]  15.29 119.76 0 bottom
NOREF#26  -  [unnamed#3]  176.27 115.85 0 bottom
NOREF#27  -  [#2]  58.21 67.31 180 bottom
NOREF#28  -  [#2]  56.05 32.64 180 bottom
NOREF#29  -  [unnamed#3]  15.29 13.72 0 bottom
Q1  LBSS139LT1G  [SOT-23]  71.75 24.61 90 top
Q2  LMBT3904LT1G  [SOT-23]  147.24 18.03 0 top
Q3  YJL2305A  [SOT-23]  18.72 89.15 0 top
Q4  LBSS139LT1G  [SOT-23]  18.72 93.22 0 top
Q5  LBSS139LT1G  [SOT-23]  57.2 29.34 180 top
Q6  LBSS139LT1G  [SOT-23]  67.94 24.61 90 top
Q7  LBSS139LT1G  [SOT-23]  76.15 22.61 0 top
Q8  LBSS139LT1G  [SOT-23]  76.12 26.29 0 top
R1  10K/6/5%  [R0603]  9.57 24.13 90 top
R2  DNP  [R0402]  8.17 24.13 90 top
R3  100K/4/5%  [R0402]  38.78 76.71 90 top
R4  10K/4/5%  [R0402]  43.61 76.33 180 top
R5  0R/4/5%  [R0402]  71.88 28.04 180 top
R6  10K/4/5%  [R0402]  43.61 77.34 0 top
R7  1K/4/5%  [R0402]  45 79.24 270 top
R8  59K/4/1%  [R0402]  43.61 79.63 180 top
R9  8.06K/4/1%  [R0402]  43.61 80.52 0 top
R10  100K/4/5%  [R0402]  34.46 30.99 90 top
R11  100K/4/5%  [R0402]  39.29 30.61 180 top
R12  0R/4/5%  [R0402]  79.55 26.04 270 top
R13  1K/4/5%  [R0402]  40.69 33.15 270 top
R14  59K/4/1%  [R0402]  39.29 33.66 180 top
R15  10K/4/5%  [R0402]  39.29 31.62 0 top
R16  8.06K/4/1%  [R0402]  39.29 34.67 0 top
R17  DNP/R0402  [R0402]  52.37 39.24 0 bottom
R18  200K/4/1%  [R0402]  56.05 38.61 180 top
R19  56K/4/1%  [R0402]  52.37 38.35 180 bottom
R20  44.2K/4/1%  [R0402]  56.05 39.5 0 top
R21  DNP  [R0402]  77.14 96.73 0 bottom
R22  56K/4/1%  [R0402]  77.14 95.71 180 bottom
R23  200K/4/1%  [R0402]  80.82 95.63 180 top
R24  100K/4/1%  [R0402]  80.82 96.52 0 top
R25  DNP  [R0402]  74.98 36.2 180 bottom
R26  DNP  [R0402]  68.88 36.2 180 bottom
R34  10K/4/5%  [R0402]  76.88 104.73 90 top
R35  10K/4/5%  [R0402]  78.02 104.73 90 top
R36  10K/4/5%  [R0402]  79.04 104.73 90 top
R37  DNP  [R0402]  82.22 104.73 90 top
R38  10K/4/5%  [R0402]  83.36 104.73 90 top
R39  10K/4/5%  [R0402]  84.5 104.73 90 top
R40  10K/4/5%  [R0402]  85.52 104.73 90 top
R41  10K/4/5%  [R0402]  96.95 94.87 90 bottom
R42  10K/4/5%  [R0402]  92.5 94.87 90 bottom
R43  10K/4/5%  [R0402]  99.61 94.87 90 bottom
R44  10K/4/5%  [R0402]  97.84 94.87 90 bottom
R45  10K/4/5%  [R0402]  98.73 94.87 90 bottom
R46  10K/4/5%  [R0402]  96.06 94.87 90 bottom
R47  10K/4/5%  [R0402]  93.39 94.87 90 bottom
R48  10K/4/5%  [R0402]  91.61 94.87 90 bottom
R49  DNP/R0402  [R0402]  94.28 94.87 90 top
R50  1K/4/5%  [R0402]  94.28 94.87 90 bottom
R51  0R/4/5%  [R0402]  89.84 94.87 270 top
R52  0R/4/5%  [R0402]  96.95 94.87 270 top
R53  0R/4/5%  [R0402]  92.5 94.87 270 top
R54  0R/4/5%  [R0402]  90.72 94.87 270 top
R55  0R/4/5%  [R0402]  99.61 94.87 270 top
R56  0R/4/5%  [R0402]  97.84 94.87 270 top
R57  0R/4/5%  [R0402]  100.5 94.87 270 top
R58  0R/4/5%  [R0402]  98.73 94.87 270 top
R59  0R/4/5%  [R0402]  96.06 94.87 270 top
R60  0R/4/5%  [R0402]  93.39 94.87 270 top
R61  0R/4/5%  [R0402]  91.61 94.87 270 top
R62  22R/4/5%  [R0402]  95.17 94.87 270 bottom
R63  DNP/R0402  [R0402]  95.17 94.87 90 top
R64  10K/4/5%  [R0402]  101.52 94.87 90 top
R65  10K/4/5%  [R0402]  90.72 94.87 90 bottom
R66  100K/4/5%  [R0402]  89.84 94.87 270 bottom
R68  10K/4/5%  [R0402]  90.85 113.28 0 top
R69  DNP  [R0402]  42.08 107.57 0 top
R70  DNP  [R0402]  42.08 108.71 0 top
R71  DNP  [R0402]  42.08 106.43 0 top
R72  DNP  [R0402]  42.08 105.28 0 top
R73  10K/4/5%  [R0402]  64.44 111.97 180 top
R74  DNP  [R0402]  42.08 103 0 top
R76  DNP  [R0402]  42.08 104.14 0 top
R77  10K/4/5%  [R0402]  45 110.49 0 top
R78  0R/4/5%  [R0402]  45 104.14 0 top
R79  0R/4/5%  [R0402]  64.44 104.86 180 top
R80  0R/4/5%  [R0402]  45 103 0 top
R81  0R/4/5%  [R0402]  64.44 103.84 180 top
R82  0R/4/5%  [R0402]  45 105.28 0 top
R83  0R/4/5%  [R0402]  45 106.43 0 top
R84  0R/4/5%  [R0402]  45 108.41 0 top
R85  0R/4/5%  [R0402]  45 107.52 0 top
R92  0R/4/5%  [R0402]  163.62 87.12 180 top
R94  4.7K/4/5%  [R0402]  163.75 79.88 0 top
R103  10K/4/5%  [R0402]  153.08 85.72 0 top
R104  22R/4/5%  [R0402]  159.56 84.45 0 top
R105  22R/4/5%  [R0402]  159.56 80.64 0 top
R106  100R/4/5%  [R0402]  153.08 84.84 180 top
R107  0R/6/5%  [R0603]  21 85.72 90 top
R108  10K/4/5%  [R0402]  16.3 89.15 90 top
R109  0R/4/5%  [R0402]  18.46 80.55 180 bottom
R110  0R/4/5%  [R0402]  19.35 49.94 180 bottom
R111  0R/4/5%  [R0402]  18.46 79.66 180 bottom
R112  100K/4/5%  [R0402]  15.29 89.15 90 top
R113  0R/4/5%  [R0402]  19.35 49.05 180 bottom
R114  0R/4/5%  [R0402]  18.46 78.64 180 bottom
R115  0R/4/5%  [R0402]  19.35 48.16 180 bottom
R116  0R/4/5%  [R0402]  18.46 77.75 180 bottom
R117  DNP  [R0603]  22.27 85.72 90 top
R118  0R/4/5%  [R0402]  19.35 50.83 180 bottom
R119  0R/4/5%  [R0402]  19.35 47.27 180 bottom
R120  0R/4/5%  [R0402]  18.46 76.86 180 bottom
R121  0R/4/5%  [R0402]  19.35 46.38 180 bottom
R122  0R/4/5%  [R0402]  18.46 75.97 180 bottom
R123  0R/4/5%  [R0402]  19.35 45.49 180 bottom
R124  0R/4/5%  [R0402]  18.46 75.08 180 bottom
R125  0R/4/5%  [R0402]  19.35 44.6 180 bottom
R126  0R/4/5%  [R0402]  18.46 74.2 180 bottom
R127  1K/4/5%  [R0402]  16.3 93.09 90 top
R128  0R/4/5%  [R0402]  19.35 43.72 180 bottom
R129  0R/4/5%  [R0402]  18.46 73.31 180 bottom
R130  0R/4/5%  [R0402]  19.35 42.83 180 bottom
R131  0R/4/5%  [R0402]  18.46 72.42 180 bottom
R132  10K/4/5%  [R0402]  15.29 93.09 90 top
R133  10K/4/5%  [R0402]  21.64 41.05 180 bottom
R134  10K/4/5%  [R0402]  20.24 70.26 180 bottom
R135  10K/4/5%  [R0402]  21.64 41.94 180 bottom
R136  10K/4/5%  [R0402]  20.24 71.15 180 bottom
R137  0R/4/5%  [R0402]  19.35 41.94 180 bottom
R138  0R/4/5%  [R0402]  18.46 71.15 180 bottom
R139  0R/4/5%  [R0402]  19.35 41.05 180 bottom
R140  0R/4/5%  [R0402]  18.46 70.26 180 bottom
R141  0R/4/5%  [R0402]  148.13 70.23 180 top
R142  22R/4/5%  [R0402]  157.27 41.02 270 top
R143  10K/4/5%  [R0402]  19.35 37.11 0 bottom
R144  0R/4/5%  [R0402]  19.35 38 180 bottom
R145  10K/4/5%  [R0402]  20.37 64.26 180 bottom
R146  0R/4/5%  [R0402]  18.46 64.26 180 bottom
R147  DNP  [R0402]  15.67 96.14 180 top
R148  0R/4/5%  [R0402]  163.18 43.31 180 bottom
R149  10K/4/5%  [R0402]  157.33 48.01 270 bottom
R150  0R/4/5%  [R0402]  163.18 44.58 180 bottom
R151  0R/4/5%  [R0402]  163.18 45.47 180 bottom
R152  0R/4/5%  [R0402]  162.35 48.01 90 bottom
R153  10K/4/5%  [R0402]  159.81 68.71 180 top
R154  10K/4/5%  [R0402]  152.32 68.71 0 top
R156  10K/4/5%  [R0402]  159.81 72.77 180 top
R157  10K/4/5%  [R0402]  152.32 72.77 0 top
R158  10K/4/5%  [R0402]  159.81 70.48 180 top
R159  10K/4/5%  [R0402]  152.32 70.48 0 top
R160  10K/4/5%  [R0402]  161.34 43.31 0 bottom
R161  0R/4/5%  [R0402]  148.51 21.72 90 top
R162  0R/4/5%  [R0402]  147.49 21.72 90 top
R163  22R/4/5%  [R0402]  141.14 27.43 0 top
R164  22R/4/5%  [R0402]  141.14 28.32 0 top
R165  22R/4/5%  [R0402]  141.14 29.21 0 top
R166  22R/4/5%  [R0402]  141.14 30.1 0 top
R167  22R/4/5%  [R0402]  141.14 30.99 0 top
R168  22R/4/5%  [R0402]  141.14 31.88 0 top
R169  22R/4/5%  [R0402]  141.14 32.77 0 top
R170  22R/4/5%  [R0402]  141.14 33.66 0 top
R171  22R/4/5%  [R0402]  141.14 34.54 0 top
R172  22R/4/5%  [R0402]  141.14 36.32 0 top
R173  22R/4/5%  [R0402]  141.14 37.21 0 top
R174  22R/4/5%  [R0402]  143.81 38.61 270 top
R175  22R/4/5%  [R0402]  144.7 38.61 270 top
R176  22R/4/5%  [R0402]  145.59 38.61 270 top
R177  22R/4/5%  [R0402]  146.48 38.61 270 top
R178  22R/4/5%  [R0402]  147.37 38.61 270 top
R179  22R/4/5%  [R0402]  148.26 38.61 270 top
R180  22R/4/5%  [R0402]  149.27 38.61 270 top
R181  22R/4/5%  [R0402]  150.29 38.61 270 top
R182  22R/4/5%  [R0402]  151.3 38.61 270 top
R183  22R/4/5%  [R0402]  152.32 38.61 270 top
R184  22R/4/5%  [R0402]  153.34 38.61 270 top
R185  22R/4/5%  [R0402]  154.35 38.61 270 top
R186  22R/4/5%  [R0402]  155.37 38.61 270 top
R190  22R/4/5%  [R0402]  156 21.72 90 bottom
R191  22R/4/5%  [R0402]  152.93 21.72 90 bottom
R192  22R/4/5%  [R0402]  150.03 69.85 270 bottom
R194  22R/4/5%  [R0402]  141.14 26.54 0 top
R195  22R/4/5%  [R0402]  141.14 24.77 0 top
R196  22R/4/5%  [R0402]  141.14 25.65 0 top
R197  1K/4/5%  [R0402]  148.26 41.02 90 top
R198  22R/4/5%  [R0402]  141.14 35.43 0 top
R199  1K/4/5%  [R0402]  149.27 41.02 90 top
R200  1K/4/5%  [R0402]  150.29 41.02 90 top
R201  1K/4/5%  [R0402]  151.3 41.02 90 top
R202  1K/4/5%  [R0402]  152.32 41.02 90 top
R203  1K/4/5%  [R0402]  153.34 41.02 90 top
R204  1K/4/5%  [R0402]  154.35 41.02 90 top
R205  1K/4/5%  [R0402]  155.37 41.02 90 top
R206  1K/4/5%  [R0402]  161.52 47.24 180 top
R207  1K/4/5%  [R0402]  161.52 49.28 180 top
R208  1K/4/5%  [R0402]  161.52 51.31 180 top
R209  1K/4/5%  [R0402]  161.52 53.34 180 top
R210  1K/4/5%  [R0402]  161.52 56.77 180 top
R211  1K/4/5%  [R0402]  161.52 58.29 180 top
R212  1K/4/5%  [R0402]  161.52 61.21 180 top
R213  1K/4/5%  [R0402]  161.52 63.25 180 top
R216  1K/4/5%  [R0402]  159.24 47.24 0 top
R217  1K/4/5%  [R0402]  159.24 50.16 0 top
R218  1K/4/5%  [R0402]  121.71 40.64 90 top
R219  1K/4/5%  [R0402]  122.98 40.64 90 top
R220  1K/4/5%  [R0402]  124.25 40.64 90 top
R221  DNP  [R0402]  159.24 51.31 0 top
R222  1K/4/5%  [R0402]  150.29 44.83 270 top
R223  1K/4/5%  [R0402]  152.32 44.83 270 top
R224  1K/4/5%  [R0402]  153.34 44.83 270 top
R225  DNP  [R0402]  154.35 44.83 270 top
R226  DNP  [R0402]  155.37 44.83 270 top
R227  1K/4/5%  [R0402]  132.13 40.64 90 top
R228  DNP  [R0402]  151.3 44.83 270 top
R229  1K/4/5%  [R0402]  120.44 40.64 90 top
R230  1K/4/5%  [R0402]  129.59 40.64 90 top
R231  1K/4/5%  [R0402]  130.86 40.64 90 top
R232  100K/4/5%  [R0402]  159.24 48.13 180 top
R233  100K/4/5%  [R0402]  159.24 49.28 180 top
R234  100K/4/5%  [R0402]  159.24 52.2 180 top
R235  100K/4/5%  [R0402]  150.29 44.83 90 bottom
R236  100K/4/5%  [R0402]  151.3 44.83 90 bottom
R237  100K/4/5%  [R0402]  152.32 44.83 90 bottom
R238  100K/4/5%  [R0402]  153.34 44.83 90 bottom
R239  DNP  [R0402]  154.35 44.83 90 bottom
R240  DNP  [R0402]  155.37 44.83 90 bottom
R241  100K/4/5%  [R0402]  120.44 54.74 90 top
R242  100K/4/5%  [R0402]  121.71 54.74 90 top
R243  100K/4/5%  [R0402]  122.98 54.74 90 top
R244  100K/4/5%  [R0402]  124.25 54.74 90 top
R245  100K/4/5%  [R0402]  129.59 54.61 90 top
R246  100K/4/5%  [R0402]  130.86 54.61 90 top
R247  100K/4/5%  [R0402]  132.13 54.61 90 top
R248  DNP  [R0402]  75.93 19.68 180 top
R249  4.99k/4/1%  [R0402]  68.69 12.95 90 top
R250  4.99k/4/1%  [R0402]  73.52 12.95 90 top
R251  0R/12/1%  [R1206]  78.15 6.35 270 top
R252  0R/4/5%  [R0402]  157.71 92.22 90 top
R253  0R/4/5%  [R0402]  153.27 108.6 180 top
R254  0R/4/5%  [R0402]  153.27 112.29 180 top
R255  60.4R/6/1%  [R0603]  153.27 109.75 180 top
R256  60.4R/6/1%  [R0603]  153.27 111.14 180 top
R257  0R/4/5%  [R0402]  155.17 92.22 90 top
R258  10K/4/5%  [R0402]  171.56 103.14 270 top
R259  DNP  [R1206]  164.64 100.33 90 bottom
R260  0R/4/5%  [R0402]  146.28 92.09 90 top
R261  0R/4/5%  [R0402]  141.59 108.48 180 top
R262  0R/4/5%  [R0402]  141.59 112.16 180 top
R263  0R/4/5%  [R0402]  143.74 92.09 90 top
R264  60.4R/6/1%  [R0603]  141.59 109.62 180 top
R265  60.4R/6/1%  [R0603]  141.59 111.02 180 top
R266  10K/4/5%  [R0402]  130.41 91.97 90 top
R267  4.7K/4/5%  [R0402]  132.57 108.99 270 top
R268  0R/4/5%  [R0402]  134.22 91.97 90 top
R269  0R/4/5%  [R0402]  131.3 91.97 90 top
R270  0R/4/5%  [R0402]  131.68 108.99 90 top
R271  DNP  [R0603]  131.3 110.51 180 top
R272  0R/4/5%  [R0402]  130.79 108.99 90 top
R273  10K/4/5%  [R0402]  113.39 103.78 270 top
R274  0R/4/5%  [R0402]  133.08 91.97 90 top
R275  4.7K/4/5%  [R0402]  129.9 108.99 90 top
R276  10K/4/5%  [R0402]  132.19 91.97 270 top
R277  DNP  [R1206]  106.47 101.22 90 bottom
R278  10K/4/5%  [R0402]  117.71 91.97 90 top
R279  4.7K/4/5%  [R0402]  120.5 108.99 270 top
R280  0R/4/5%  [R0402]  121.52 91.97 90 top
R281  0R/4/5%  [R0402]  119.61 108.99 90 top
R282  DNP  [R0603]  119.23 110.51 180 top
R283  0R/4/5%  [R0402]  118.6 91.97 90 top
R284  0R/4/5%  [R0402]  118.73 108.99 90 top
R285  0R/4/5%  [R0402]  120.38 91.97 90 top
R286  4.7K/4/5%  [R0402]  117.84 108.99 90 top
R287  10K/4/5%  [R0402]  119.49 91.97 270 top
R288  22R/4/5%  [R0402]  49.32 22.73 270 top
R289  10K/4/5%  [R0402]  51.35 19.81 0 top
R290  0R/4/5%  [R0402]  44.88 27.43 270 top
R291  0R/4/5%  [R0402]  45.77 27.43 270 top
R292  0R/4/5%  [R0402]  48.43 27.43 270 top
R293  0R/4/5%  [R0402]  46.66 27.43 270 top
R294  0R/4/5%  [R0402]  49.32 27.43 270 top
R295  0R/4/5%  [R0402]  47.54 27.43 270 top
R297  2.37K/4/1%  [R0402]  47.37 16.74 90 top
R298  DNP  [R0402]  37.38 20.57 180 top
R299  4.7K/4/5%  [R0402]  43.38 24.54 180 bottom
R300  10K/4/5%  [R0402]  128.06 36.45 270 top
R301  DNP  [R0402]  132 36.45 270 top
R302  0R/4/5%  [R0402]  131.11 36.45 90 top
R303  10K/4/5%  [R0402]  133.78 36.45 90 top
R304  100K/4/5%  [R0402]  137.59 33.53 180 top
R305  10K/4/5%  [R0402]  137.59 32.64 180 top
R306  100K/4/5%  [R0402]  137.59 31.75 180 top
R307  2.7K/4/1%  [R0402]  137.59 28.32 0 top
R308  10K/4/5%  [R0402]  60.75 20.57 180 top
R309  10K/4/5%  [R0402]  55.55 19.56 0 top
R310  10K/4/5%  [R0402]  60.75 19.68 180 top
R311  10K/4/5%  [R0402]  55.55 18.54 0 top
R312  DNP  [R0402]  60.75 17.91 180 top
R313  DNP  [R0402]  60.75 17.02 0 top
R314  0R/4/5%  [R0402]  53.66 12.95 270 top
R315  0R/4/5%  [R0402]  58.44 13.08 270 top
R316  10K/4/5%  [R0402]  54.78 29.46 270 top
R317  DNP  [R0402]  53.89 29.46 90 top
R318  10K/4/5%  [R0402]  59.74 26.29 0 bottom
R319  0R/4/5%  [R0402]  59.61 29.46 90 top
R320  0R/12/1%  [R1206]  51.48 11.94 270 top
R321  0R/12/1%  [R1206]  144.45 14.73 90 bottom
R322  10K/4/5%  [R0402]  72.56 102.74 90 bottom
R323  0R/4/5%  [R0402]  67.23 102.74 90 bottom
R324  100K/4/5%  [R0402]  41.96 62.74 180 top
R325  22R/4/5%  [R0402]  73.58 102.74 270 bottom
R326  22R/4/5%  [R0402]  70.28 102.74 270 bottom
R327  22R/4/5%  [R0402]  75.23 102.74 270 bottom
R328  110K/4/1%  [R0402]  34.59 62.36 0 top
R329  36K/4/1%  [R0402]  41.96 63.63 0 top
R330  20K/4/1%  [R0402]  34.59 64.14 180 top
R331  10K/4/5%  [R0402]  92.25 102.74 90 bottom
R332  22R/4/5%  [R0402]  89.96 102.74 270 bottom
R333  22R/4/5%  [R0402]  94.92 102.74 270 bottom
R334  0R/4/5%  [R0402]  86.91 102.74 90 bottom
R335  22R/4/5%  [R0402]  93.26 102.74 270 bottom
R336  10K/4/5%  [R0402]  30.27 45.59 90 bottom
R337  10K/4/5%  [R0402]  29.38 45.59 90 bottom
R338  10K/4/5%  [R0402]  26.97 45.59 90 bottom
R339  10K/4/5%  [R0402]  45.77 45.59 90 bottom
R340  10K/4/5%  [R0402]  44.5 45.59 90 bottom
R341  10K/4/5%  [R0402]  32.3 45.59 90 bottom
R342  10K/4/5%  [R0402]  31.29 45.59 90 bottom
R343  DNP  [R0402]  46.78 45.59 270 bottom
R344  1K/4/5%  [R0402]  97.11 24 270 top
R345  470R/4/5%  [R0402]  81.62 24.23 270 top
R346  DNP  [R0402]  95.72 29.18 180 top
R347  2.2K/4/5%  [R0402]  95.72 30.07 180 top
R348  0R/4/5%  [R0402]  95.72 35.4 0 top
R349  0R/4/5%  [R0402]  95.72 34.52 0 top
R350  0R/4/5%  [R0402]  95.72 32.74 0 top
R351  0R/4/5%  [R0402]  95.72 31.85 0 top
R352  0R/4/5%  [R0402]  95.72 33.63 0 top
R353  0R/4/5%  [R0402]  95.72 30.96 0 top
R354  0R/4/5%  [R0402]  90.89 38.86 90 top
R355  0R/4/5%  [R0402]  91.91 38.86 90 top
R356  0R/4/5%  [R0402]  93.94 38.86 90 top
R357  0R/4/5%  [R0402]  95.72 37.18 0 top
R358  0R/4/5%  [R0402]  92.92 38.86 90 top
R359  0R/4/5%  [R0402]  95.72 36.29 0 top
R360  4.7K/4/5%  [R0402]  84.67 38.83 270 top
R361  10K/4/5%  [R0402]  73.11 38.99 180 bottom
R362  2.49K/4/1%  [R0402]  82.38 28.19 180 top
R363  10K/4/5%  [R0402]  74.98 37.21 0 bottom
R364  10K/4/5%  [R0402]  82 38.83 270 top
R365  DNP  [R0402]  82.89 38.83 270 top
R366  DNP  [R0402]  82 38.83 90 bottom
R367  4.7K/4/5%  [R0402]  82.89 38.83 90 bottom
R368  4.7K/4/5%  [R0402]  91.14 38.86 270 bottom
R369  DNP  [R0402]  90.25 38.86 270 bottom
R370  4.7K/4/5%  [R0402]  83.78 38.83 270 top
R371  4.7K/4/5%  [R0402]  92.92 38.86 270 bottom
R372  DNP  [R0402]  93.81 38.86 90 bottom
R373  DNP  [R0402]  83.78 38.83 90 bottom
R374  4.7K/4/5%  [R0402]  89.37 38.86 90 bottom
R375  DNP  [R0402]  92.03 38.86 90 bottom
R376  4.7K/4/5%  [R0402]  94.7 38.86 90 bottom
R377  4.7K/4/5%  [R0402]  95.72 37.18 0 bottom
R378  4.7K/4/5%  [R0402]  95.72 36.29 0 bottom
R379  1K/4/5%  [R0402]  119.26 24.36 270 top
R380  470R/4/5%  [R0402]  104.28 24.36 270 top
R381  DNP  [R0402]  119.01 29.18 180 top
R382  2.2K/4/5%  [R0402]  119.01 30.07 180 top
R383  0R/4/5%  [R0402]  119.01 33.63 0 top
R384  0R/4/5%  [R0402]  119.01 31.85 0 top
R385  0R/4/5%  [R0402]  119.01 30.96 0 top
R386  0R/4/5%  [R0402]  119.01 35.4 0 top
R387  0R/4/5%  [R0402]  119.01 34.52 0 top
R388  0R/4/5%  [R0402]  119.01 32.74 0 top
R389  0R/4/5%  [R0402]  114.18 38.86 90 top
R390  0R/4/5%  [R0402]  115.07 38.86 90 top
R391  0R/4/5%  [R0402]  115.96 38.86 90 top
R392  0R/4/5%  [R0402]  116.85 38.86 90 top
R393  0R/4/5%  [R0402]  119.01 37.18 0 top
R394  0R/4/5%  [R0402]  119.01 36.29 0 top
R395  4.7K/4/5%  [R0402]  107.96 38.83 270 top
R396  10K/4/5%  [R0402]  67.1 38.96 180 bottom
R397  2.49K/4/1%  [R0402]  105.67 28.19 180 top
R398  10K/4/5%  [R0402]  68.88 37.18 0 bottom
R399  10K/4/5%  [R0402]  105.29 38.83 270 top
R400  DNP  [R0402]  106.18 38.83 270 top
R401  DNP  [R0402]  105.29 38.83 90 bottom
R402  4.7K/4/5%  [R0402]  106.18 38.83 90 bottom
R403  DNP  [R0402]  114.18 38.86 270 bottom
R404  DNP  [R0402]  113.29 38.86 270 bottom
R405  4.7K/4/5%  [R0402]  107.07 38.83 270 top
R406  4.7K/4/5%  [R0402]  115.96 38.86 270 bottom
R407  DNP  [R0402]  116.85 38.86 90 bottom
R408  DNP  [R0402]  107.07 38.83 90 bottom
R409  4.7K/4/5%  [R0402]  112.4 38.86 90 bottom
R410  4.7K/4/5%  [R0402]  115.07 38.86 90 bottom
R411  4.7K/4/5%  [R0402]  117.74 38.86 90 bottom
R412  4.7K/4/5%  [R0402]  119.01 37.18 0 bottom
R413  4.7K/4/5%  [R0402]  119.01 36.29 0 bottom
R414  4.7K/4/5%  [R0402]  161.78 14.22 180 bottom
R416  100K/4/5%  [R0402]  161.72 21.97 180 bottom
R417  100K/4/5%  [R0402]  161.72 31.75 0 top
R419  10K/4/5%  [R0402]  115.62 63.75 180 top
R423  470R/4/5%  [R0402]  93.39 117.68 90 top
R424  470R/4/5%  [R0402]  101.65 117.68 90 top
R426  470R/4/5%  [R0402]  98.98 117.68 90 top
R427  470R/4/5%  [R0402]  96.31 117.68 90 top
R428  10K/4/5%  [R0402]  159.81 74.55 180 bottom
R429  10K/4/5%  [R0402]  152.32 74.55 0 bottom
R431  10K/4/5%  [R0402]  157.27 38.61 270 bottom
R432  10K/4/5%  [R0402]  156.38 38.61 270 bottom
R433  10K/4/5%  [R0402]  154.86 21.72 90 bottom
R434  10K/4/5%  [R0402]  44.88 27.43 270 bottom
R435  10K/4/5%  [R0402]  45.77 27.43 270 bottom
R437  10K/4/5%  [R0402]  19.35 40.16 180 bottom
R438  10K/4/5%  [R0402]  148.13 67.56 180 top
R444  0R/4/5%  [R0402]  152.32 74.55 0 top
R445  0R/4/5%  [R0402]  157.27 38.61 270 top
R449  0R/4/5%  [R0402]  19.35 39.27 180 bottom
R451  0R/4/5%  [R0402]  18.46 65.28 180 bottom
R452  0R/4/5%  [R0402]  159.81 74.55 180 top
R453  0R/4/5%  [R0402]  115.62 70.36 0 top
R454  0R/4/5%  [R0402]  57.77 21.46 270 top
R456  10K/4/5%  [R0402]  148.13 70.23 180 bottom
R460  10K/4/5%  [R0402]  148.13 69.34 180 bottom
R461  0R/4/5%  [R0402]  148.13 69.34 180 top
R467  10K/4/5%  [R0402]  18.46 66.29 180 bottom
R468  10K/4/5%  [R0402]  18.46 68.33 180 bottom
R470  10K/4/5%  [R0402]  115.62 70.36 0 bottom
R471  10K/4/5%  [R0402]  129.21 70.36 180 bottom
R473  10K/4/5%  [R0402]  57.77 21.46 270 bottom
R474  10K/4/5%  [R0402]  58.66 21.46 270 bottom
R487  22R/4/5%  [R0402]  137.59 30.86 180 top
R489  0R/4/5%  [R0402]  156.38 38.61 270 top
R491  0R/4/5%  [R0402]  148.13 68.45 180 top
R492  0R/4/5%  [R0402]  18.46 67.31 180 bottom
R493  0R/4/5%  [R0402]  129.21 70.36 180 top
R494  0R/4/5%  [R0402]  58.66 21.46 270 top
R498  10K/4/5%  [R0402]  135.81 70.87 0 top
R502  0R/4/5%  [R0402]  61.05 117.36 180 top
R504  0R/4/5%  [R0402]  49.58 117.36 0 top
R511  DNP  [R0402]  55.42 94.36 90 top
R512  DNP  [R0402]  52.5 96.52 0 top
R513  DNP  [R0402]  54.28 96.52 0 top
R514  4.7K/4/5%  [R0402]  157.4 35.94 180 top
R515  0R/4/5%  [R0402]  141.14 23.88 180 top
R516  0R/4/5%  [R0402]  146.48 21.72 90 top
R517  0R/4/5%  [R0402]  157.4 35.05 0 top
R518  4.3K/4/1%  [R0402]  150.67 17.91 90 top
R521  1K/4/5%  [R0402]  145.21 52.7 0 top
R522  DNP/R0402  [R0402]  151.68 14.22 270 top
R523  DNP/R0402  [R0402]  150.8 14.22 270 top
R524  100K/4/5%  [R0402]  144.95 17.91 90 top
R525  100K/4/5%  [R0402]  144.06 17.91 90 top
R526  0R/12/1%  [R1206]  164 8.51 270 top
R527  100K/4/5%  [R0402]  149.65 17.91 90 top
R528  DNP  [R0402]  145.21 48.13 180 top
R529  DNP  [R0402]  153.21 49.02 0 top
R530  DNP  [R0402]  149.58 50.27 180 bottom
R531  DNP  [R0402]  145.21 50.8 0 top
R532  0R/4/5%  [R0402]  153.21 48.13 180 top
R533  0R/4/5%  [R0402]  145.21 49.02 0 top
R534  0R/4/5%  [R0402]  144.45 23.5 180 top
R535  10K/4/5%  [R0402]  140.89 21.21 270 top
R536  0.01R/12/1%  [R1206]  67.86 95.89 90 top
R537  10K/4/5%  [R0402]  153.97 21.72 90 bottom
R539  10K/4/5%  [R0402]  129.21 66.55 180 top
R540  0R/4/5%  [R0402]  163.75 78.99 0 top
R542  0R/4/5%  [R0402]  95.72 29.18 180 bottom
R543  0R/4/5%  [R0402]  95.72 30.07 180 bottom
R544  100K/4/5%  [R0402]  77.14 97.66 0 bottom
R545  100K/4/5%  [R0402]  145.21 53.59 180 top
R554  22R/4/5%  [R0402]  20.37 65.28 180 bottom
R555  10K/4/5%  [R0402]  64.05 31.5 180 top
R557  10K/4/5%  [R0402]  79.04 34.8 180 top
R558  10K/4/5%  [R0402]  71.88 27.15 180 top
R559  10K/4/5%  [R0402]  68.07 27.15 0 top
R560  0R/4/5%  [R0402]  68.07 28.04 0 top
R561  10K/4/5%  [R0402]  78.69 22.48 90 top
R562  0R/4/5%  [R0402]  79.57 22.48 90 top
R563  10K/4/5%  [R0402]  78.66 26.04 270 top
R567  1K/4/5%  [R0402]  79.04 35.69 0 top
R569  2.37K/4/1%  [R0402]  42.08 16.76 90 top
R570  0R/6/5%  [R0603]  47.14 4.29 90 top
R571  22R/4/5%  [R0402]  161.52 55.5 180 top
R572  22R/4/5%  [R0402]  161.46 60.33 180 top
R573  100K/4/5%  [R0402]  52.37 36.58 0 bottom
R574  0R/12/1%  [R1206]  101.14 15.6 90 top
R575  0R/12/1%  [R1206]  122.96 17.45 90 top
S1  -  [SKRAAME010]  167.75 17.27 180 top
S2  -  [SKRAAME010]  167.75 25.15 180 top
S3  -  [SKRAAME010]  167.75 32.38 180 top
SW1  SS-12D10-L9-B  [SW-SS-12D10-L9-B]  10.59 16 90 top
SW2  218-4LPSTR  [SW-2X4]  122.35 47.75 0 top
SW3  218-4LPSTR  [SW-2X4]  131.49 47.75 0 top
TEMPLATE1  TEMPLATE_A2  [TEMPLATE-A2]  -66.25 -153.92 0 top
TP1  SMD  [HOLE-TP0_9S16]  12.37 25.4 0 top
TP2  SMD  [HOLE-TP0_9S16]  20.37 30.1 0 top
TP3  SMD  [TEST0_8-SMD]  40.18 76.71 0 top
